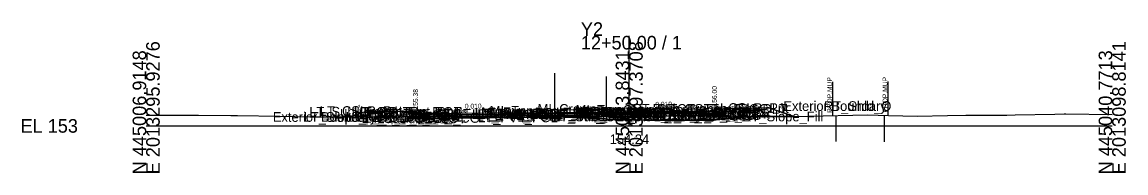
# Model space of a CAD drawing. Extents: x -26 to 203, y -10 to 6017.
# Drawn here: x -25.7 to 202.8, y 4990.3 to 5021.4 of the extents above; entities that cross this region are included whole.
import ezdxf

# ---------------------------------------------------------------- set-up
doc = ezdxf.new("R2010")
doc.units = 0
for name, color, linetype in [('Default', 7, 'Continuous'), ('Exist Cross Section Cell', 7, 'Continuous'), ('Exist XS Center Line Elevation Label', 7, 'Continuous'), ('Exist XS Ground Line', 7, 'Continuous'), ('Prop CMT Conc Surface', 7, 'Continuous'), ('Prop CMT Concrete Structures', 7, 'Continuous'), ('Prop CMT Pvmt Course 1', 7, 'Continuous'), ('Prop CMT Pvmt Course 1 CG', 7, 'Continuous'), ('Prop CMT Pvmt Course 1 Wedge', 7, 'Continuous'), ('Prop CMT Pvmt Course 2', 7, 'Continuous'), ('Prop CMT Pvmt Course 2 Wedge', 7, 'Continuous'), ('Prop CMT Pvmt Course 3', 7, 'Continuous'), ('Prop CMT Pvmt Surface', 7, 'Continuous'), ('Prop CMT Pvmt Wedge Surface 1', 7, 'Continuous'), ('Prop CMT Pvmt Wedge Surface 2', 7, 'Continuous'), ('Prop CMT Slope Grass', 7, 'Continuous'), ('Prop CMT Subgrade Earthwork', 7, 'Continuous'), ('Prop XS Earthwork Shape', 7, 'Continuous'), ('Prop XS Hydro Elevations', 7, 'Continuous'), ('Prop XS Label Text', 7, 'Continuous'), ('Prop XS SE Text', 7, 'Continuous'), ('Prop XS Side Slope Text', 7, 'Continuous'), ('Scratch_Level_0', 7, 'Continuous'), ('Scratch_Level_1', 7, 'Continuous'), ('Scratch_Level_3', 7, 'Continuous')]:
    doc.layers.add(name, color=color, linetype=linetype)

msp = doc.modelspace()

# ---------------------------------------------------------------- linework, layer by layer
at = {"layer": 'Exist Cross Section Cell'}
for p, q in [((100, 5000), (100, 5018.58)), ((0, 5000), (100, 5000)), ((100, 5000), (200, 5000))]:
    msp.add_line(p, q, dxfattribs=at)
at = {"layer": 'Exist XS Ground Line'}
msp.add_lwpolyline([(0, 5002.23), (6.99, 5002.25), (7.99, 5002.25), (10.86, 5002.24), (17.52, 5002.15), (18.9, 5002.15), (27.67, 5001.99), (33.86, 5001.88), (37.81, 5001.86), (43.4, 5001.84), (47.96, 5001.87), (55.66, 5001.97), (58.11, 5001.97), (67.91, 5001.92), (68.26, 5001.92), (69.94, 5001.96), (78.4, 5002.12), (79.89, 5002.1), (94.98, 5001.45), (96.16, 5001.33), (97.05, 5001.27), (100, 5001.24), (103.04, 5001.21), (107.68, 5001.17), (115.74, 5001.2), (117.56, 5001.19), (118.76, 5001.39), (119.14, 5001.44), (120.7, 5001.58), (125.45, 5001.92), (126.09, 5001.92), (132.22, 5001.92), (133.71, 5001.96), (137.05, 5002.02), (149.44, 5002.29), (153.67, 5002.17), (159.59, 5002.04), (165.92, 5002.17), (169.73, 5002.19), (178.18, 5002.25), (179.88, 5002.3), (188.1, 5002.44), (190.03, 5002.48), (190.43, 5002.48), (200, 5002.35)], dxfattribs=at)
at = {"layer": 'Prop CMT Conc Surface'}
for points in [[(51.26, 5002.97), (46.26, 5003.07)], [(55.76, 5002.38), (55.76, 5002.88), (55.26, 5002.88)], [(115.65, 5003.06), (117.65, 5003)], [(117.65, 5003), (117.66, 5003.5), (118.16, 5003.5)], [(57.76, 5002.48), (55.76, 5002.38)]]:
    msp.add_lwpolyline(points, dxfattribs=at)
at = {"layer": 'Prop CMT Concrete Structures'}
for p, q in [((84.64, 5002.92), (84.63, 5002.75)), ((85.39, 5003.17), (84.64, 5002.92)), ((90.11, 5003.36), (85.39, 5003.17)), ((94.57, 5003.27), (90.11, 5003.36)), ((95.32, 5003.02), (94.57, 5003.27)), ((95.33, 5002.86), (95.32, 5003.02))]:
    msp.add_line(p, q, dxfattribs=at)
for points in [[(46.26, 5002.74), (46.26, 5003.07)], [(46.26, 5003.07), (51.26, 5002.97)], [(51.26, 5002.64), (46.26, 5002.74)], [(51.26, 5002.97), (51.26, 5002.64)], [(57.76, 5002.48), (55.76, 5002.38), (55.76, 5002.88), (55.26, 5002.88)], [(55.26, 5002.88), (55.26, 5001.87), (57.76, 5001.9)], [(77.51, 5002.68), (98.45, 5002.89)], [(115.65, 5003.06), (117.65, 5003), (117.66, 5003.5), (118.16, 5003.5)], [(118.16, 5003.5), (118.15, 5002.5), (115.65, 5002.48)], [(115.65, 5002.48), (115.65, 5003.06)], [(128.43, 5003.72), (122.8, 5003.6)], [(122.8, 5003.6), (122.8, 5003.27)], [(122.8, 5003.27), (128.43, 5003.38)], [(128.43, 5003.38), (128.43, 5003.72)], [(57.76, 5001.9), (57.76, 5002.48)]]:
    msp.add_lwpolyline(points, dxfattribs=at)
at = {"layer": 'Prop CMT Pvmt Course 1'}
for points in [[(77.51, 5002.68), (57.76, 5002.48)], [(77.51, 5002.68), (98.45, 5002.89)], [(77.51, 5002.43), (77.51, 5002.68)], [(77.51, 5002.43), (77.51, 5002.68)], [(98.45, 5002.64), (77.51, 5002.43)], [(98.45, 5002.89), (115.65, 5003.06)], [(98.45, 5002.64), (98.45, 5002.89)], [(98.45, 5002.89), (98.45, 5002.64)], [(98.45, 5002.76), (98.45, 5002.64), (98.45, 5002.64)], [(115.65, 5002.81), (114.57, 5002.8)], [(115.65, 5003.06), (115.65, 5002.81)], [(57.76, 5002.48), (57.76, 5002.23)], [(57.76, 5002.23), (77.51, 5002.43)], [(77.51, 5002.55), (77.51, 5002.43), (77.51, 5002.43)]]:
    msp.add_lwpolyline(points, dxfattribs=at)
at = {"layer": 'Prop CMT Pvmt Course 1 CG'}
for points in [[(57.76, 5001.9), (54.76, 5001.87), (54.42, 5001.53)], [(54.42, 5001.53), (57.76, 5001.56)], [(57.76, 5001.65), (57.76, 5001.9)], [(115.65, 5002.48), (118.65, 5002.51), (118.98, 5002.18)], [(115.65, 5002.23), (115.65, 5002.48)], [(118.98, 5002.18), (115.65, 5002.14)]]:
    msp.add_lwpolyline(points, dxfattribs=at)
at = {"layer": 'Prop CMT Pvmt Course 1 Wedge'}
for points in [[(114.57, 5002.8), (107.68, 5002.73), (103.04, 5002.68), (98.45, 5002.64)], [(98.45, 5002.64), (98.45, 5002.76)]]:
    msp.add_lwpolyline(points, dxfattribs=at)
at = {"layer": 'Prop CMT Pvmt Course 2'}
for points in [[(77.51, 5002.43), (98.45, 5002.64)], [(98.45, 5002.64), (98.45, 5002.3)], [(114.57, 5002.8), (115.65, 5002.81)], [(114.57, 5002.47), (114.57, 5002.8)], [(115.65, 5002.81), (115.65, 5002.48)], [(77.51, 5002.43), (57.76, 5002.23)], [(57.76, 5002.23), (57.76, 5001.9)], [(57.76, 5001.9), (77.51, 5002.09)], [(77.51, 5002.09), (77.51, 5002.43)], [(98.45, 5002.3), (77.51, 5002.09)], [(115.65, 5002.48), (114.57, 5002.47)]]:
    msp.add_lwpolyline(points, dxfattribs=at)
at = {"layer": 'Prop CMT Pvmt Course 2 Wedge'}
for points in [[(98.45, 5002.64), (103.04, 5002.68), (107.68, 5002.73), (114.57, 5002.8)], [(98.45, 5002.3), (98.45, 5002.64)], [(114.57, 5002.8), (114.57, 5002.47)], [(114.57, 5002.47), (107.68, 5002.4), (103.04, 5002.35), (98.45, 5002.3)]]:
    msp.add_lwpolyline(points, dxfattribs=at)
at = {"layer": 'Prop CMT Pvmt Course 3'}
for points in [[(77.51, 5002.09), (57.76, 5001.9)], [(57.76, 5001.9), (57.76, 5001.56)], [(57.76, 5001.56), (77.51, 5001.76)], [(77.51, 5002.09), (98.45, 5002.3)], [(77.51, 5001.76), (77.51, 5002.09)], [(98.45, 5001.97), (77.51, 5001.76)], [(98.45, 5002.3), (98.45, 5001.97)], [(98.45, 5001.97), (118.2, 5002.17)], [(114.57, 5002.47), (115.65, 5002.48)], [(114.57, 5002.13), (114.57, 5002.47)], [(115.65, 5002.14), (114.57, 5002.13)], [(115.65, 5002.48), (115.65, 5002.14)]]:
    msp.add_lwpolyline(points, dxfattribs=at)
at = {"layer": 'Prop CMT Pvmt Surface'}
for points in [[(77.51, 5002.68), (57.76, 5002.48)], [(77.51, 5002.68), (98.45, 5002.89)], [(98.45, 5002.89), (115.65, 5003.06)]]:
    msp.add_lwpolyline(points, dxfattribs=at)
at = {"layer": 'Prop CMT Pvmt Wedge Surface 1'}
for points in [[(98.45, 5002.89), (98.45, 5002.64), (98.45, 5002.64), (98.45, 5002.76)], [(114.57, 5002.8), (115.65, 5002.81)], [(115.65, 5002.81), (115.65, 5003.06)]]:
    msp.add_lwpolyline(points, dxfattribs=at)
at = {"layer": 'Prop CMT Pvmt Wedge Surface 2'}
for points in [[(98.45, 5002.89), (98.45, 5002.64)], [(98.45, 5002.64), (115.65, 5002.81)], [(115.65, 5002.81), (115.65, 5003.06)]]:
    msp.add_lwpolyline(points, dxfattribs=at)
at = {"layer": 'Prop CMT Slope Grass'}
for points in [[(55.26, 5002.88), (45.76, 5003.07), (42.08, 5001.84)], [(118.16, 5003.5), (128.93, 5003.72)], [(128.93, 5003.72), (134.18, 5001.97)]]:
    msp.add_lwpolyline(points, dxfattribs=at)
at = {"layer": 'Prop CMT Subgrade Earthwork'}
for points in [[(57.76, 5001.56), (54.42, 5001.53), (53.03, 5002.92)], [(115.65, 5002.14), (118.98, 5002.18), (120.35, 5003.54)], [(77.51, 5001.76), (57.76, 5001.56)], [(77.51, 5001.76), (98.45, 5001.97)], [(114.57, 5002.13), (98.45, 5001.97)], [(114.57, 5002.13), (115.65, 5002.14)]]:
    msp.add_lwpolyline(points, dxfattribs=at)
at = {"layer": 'Prop XS Earthwork Shape'}
for points in [[(54, 5001.95), (53.03, 5002.93), (45.76, 5003.07), (42.08, 5001.84), (43.4, 5001.84), (47.96, 5001.87)], [(42.08, 5001.84), (43.4, 5001.84), (47.96, 5001.87), (54, 5001.95), (53.03, 5002.93), (45.76, 5003.07)], [(54, 5001.95), (53.03, 5002.93), (45.76, 5003.07), (42.08, 5001.84), (43.4, 5001.84), (47.96, 5001.87)], [(45.76, 5003.07), (42.08, 5001.84), (43.4, 5001.84), (47.96, 5001.87), (54, 5001.95), (53.03, 5002.93)], [(97.05, 5001.27), (100, 5001.24), (103.04, 5001.21), (107.68, 5001.17), (115.74, 5001.2), (117.56, 5001.19), (118.76, 5001.39), (119.14, 5001.44), (120.7, 5001.58), (125.45, 5001.92), (126.09, 5001.92), (132.22, 5001.92), (133.71, 5001.96), (134.18, 5001.97), (128.93, 5003.72), (128.43, 5003.71), (128.43, 5003.38), (122.8, 5003.27), (122.8, 5003.59), (120.35, 5003.54), (118.98, 5002.18), (115.65, 5002.14), (114.57, 5002.13), (98.45, 5001.97), (85.88, 5001.85), (94.98, 5001.45), (96.16, 5001.33)], [(128.43, 5003.71), (128.93, 5003.72), (134.18, 5001.97), (133.71, 5001.96), (132.22, 5001.92), (126.09, 5001.92), (125.45, 5001.92), (120.7, 5001.58), (119.14, 5001.44), (118.76, 5001.39), (117.56, 5001.19), (115.74, 5001.2), (107.68, 5001.17), (103.04, 5001.21), (100, 5001.24), (97.05, 5001.27), (96.16, 5001.33), (94.98, 5001.45), (85.88, 5001.85), (98.45, 5001.97), (114.57, 5002.13), (115.65, 5002.14), (118.98, 5002.18), (120.35, 5003.54), (122.8, 5003.59), (122.8, 5003.27), (128.43, 5003.38)], [(97.05, 5001.27), (100, 5001.24), (103.04, 5001.21), (107.68, 5001.17), (115.74, 5001.2), (117.56, 5001.19), (118.76, 5001.39), (119.14, 5001.44), (120.7, 5001.58), (125.45, 5001.92), (126.09, 5001.92), (132.22, 5001.92), (133.71, 5001.96), (134.18, 5001.97), (128.93, 5003.72), (128.43, 5003.71), (128.43, 5003.38), (122.8, 5003.27), (122.8, 5003.59), (120.35, 5003.54), (118.98, 5002.18), (115.65, 5002.14), (114.57, 5002.13), (98.45, 5001.97), (85.88, 5001.85), (94.98, 5001.45), (96.16, 5001.33)], [(100, 5001.24), (103.04, 5001.21), (107.68, 5001.17), (115.74, 5001.2), (117.56, 5001.19), (118.76, 5001.39), (119.14, 5001.44), (120.7, 5001.58), (125.45, 5001.92), (126.09, 5001.92), (132.22, 5001.92), (133.71, 5001.96), (134.18, 5001.97), (128.93, 5003.72), (128.43, 5003.71), (128.43, 5003.38), (122.8, 5003.27), (122.8, 5003.59), (120.35, 5003.54), (118.98, 5002.18), (115.65, 5002.14), (114.57, 5002.13), (98.45, 5001.97), (85.88, 5001.85), (94.98, 5001.45), (96.16, 5001.33), (97.05, 5001.27)], [(54, 5001.95), (55.26, 5001.97), (55.26, 5001.87), (57.76, 5001.9), (57.76, 5001.97), (58.11, 5001.97), (67.91, 5001.92), (68.26, 5001.92), (69.94, 5001.96), (78.4, 5002.12), (79.89, 5002.1), (85.88, 5001.85), (77.51, 5001.76), (57.76, 5001.56), (54.42, 5001.53)], [(54, 5001.95), (55.26, 5001.97), (55.26, 5001.87), (57.76, 5001.9), (57.76, 5001.97), (58.11, 5001.97), (67.91, 5001.92), (68.26, 5001.92), (69.94, 5001.96), (78.4, 5002.12), (79.89, 5002.1), (85.88, 5001.85), (77.51, 5001.76), (57.76, 5001.56), (54.42, 5001.53)], [(54, 5001.95), (55.26, 5001.97), (55.26, 5001.87), (57.76, 5001.9), (57.76, 5001.97), (58.11, 5001.97), (67.91, 5001.92), (68.26, 5001.92), (69.94, 5001.96), (78.4, 5002.12), (79.89, 5002.1), (85.88, 5001.85), (77.51, 5001.76), (57.76, 5001.56), (54.42, 5001.53)], [(54, 5001.95), (55.26, 5001.97), (55.26, 5001.87), (57.76, 5001.9), (57.76, 5001.97), (58.11, 5001.97), (67.91, 5001.92), (68.26, 5001.92), (69.94, 5001.96), (78.4, 5002.12), (79.89, 5002.1), (85.88, 5001.85), (77.51, 5001.76), (57.76, 5001.56), (54.42, 5001.53)], [(55.66, 5001.97), (57.76, 5001.97), (57.76, 5001.9), (55.26, 5001.87), (55.26, 5001.97)], [(55.66, 5001.97), (57.76, 5001.97), (57.76, 5001.9), (55.26, 5001.87), (55.26, 5001.97)], [(55.66, 5001.97), (57.76, 5001.97), (57.76, 5001.9), (55.26, 5001.87), (55.26, 5001.97)], [(55.66, 5001.97), (57.76, 5001.97), (57.76, 5001.9), (55.26, 5001.87), (55.26, 5001.97)]]:
    msp.add_lwpolyline(points, close=True, dxfattribs=at)
at = {"layer": 'Prop XS Label Text'}
for p, q in [((142.11, 5009.13), (142.11, 5002.13)), ((153.57, 5009.17), (153.57, 5002.17))]:
    msp.add_line(p, q, dxfattribs=at)
at = {"layer": 'Scratch_Level_1'}
for p, q in [((142.78, 5002.14), (142.78, 4996.79)), ((152.79, 5002.19), (152.79, 4996.68))]:
    msp.add_line(p, q, dxfattribs=at)
at = {"layer": 'Scratch_Level_3'}
for p, q in [((84.63, 5002.75), (84.63, 5010.88)), ((95.33, 5002.86), (95.33, 5010.19))]:
    msp.add_line(p, q, dxfattribs=at)

# ---------------------------------------------------------------- texts
at = {"layer": 'Default'}
msp.add_text('-', height=0.0001, dxfattribs=at).set_placement((0, 5000))
at = {"layer": 'Exist Cross Section Cell'}
for s, p in [('Y2', (90, 5018.58)), ('12+50.00 / 1', (90, 5015.78)), ('EL 153', (-26, 4998.6))]:
    msp.add_text(s, height=2.8, dxfattribs=at).set_placement(p)
for s, p in [('E 2013295.9276', (2.8, 4990)), ('E 2013197.3708', (102.8, 4990)), ('E 2013098.8141', (202.8, 4990)), ('N 445006.9148', (0, 4990)), ('N 445023.8431', (100, 4990)), ('N 445040.7713', (200, 4990))]:
    msp.add_text(s, height=2.8, rotation=90, dxfattribs=at).set_placement(p)
at = {"layer": 'Exist XS Center Line Elevation Label'}
msp.add_text('154.24', height=2, dxfattribs=at).set_placement((95.96, 4996.24))
at = {"layer": 'Prop XS Hydro Elevations'}
for s, p in [('155.38', (56.26, 5003.38)), ('156.00', (118.15, 5004))]:
    msp.add_text(s, height=1, rotation=90, dxfattribs=at).set_placement(p)
at = {"layer": 'Prop XS Label Text'}
for p in [(142.01, 5002.7), (153.47, 5002.75)]:
    msp.add_text('PROP.MUP', height=1, rotation=90, dxfattribs=at).set_placement(p)
at = {"layer": 'Prop XS SE Text'}
for p in [(105.41, 5003.96), (65.99, 5003.56)]:
    msp.add_text('0.010', height=1, rotation=0.5729, dxfattribs=at).set_placement(p)
at = {"layer": 'Prop XS Side Slope Text'}
for rotation, p in [(18.4349, (42.93, 5002.92)), (341.5651, (131.04, 5003.8))]:
    msp.add_text('3:1', height=1, rotation=rotation, dxfattribs=at).set_placement(p)
at = {"layer": 'Scratch_Level_0'}
for s, p in [('Exterior Boundary', (131.92, 5003.09)), ('RT_Shld_O', (140.31, 5003.09)), ('Exterior Boundary', (26.22, 5000.84)), ('LT_Slope_Fill', (32.6, 5000.84)), ('LT_Sub_Trench_Out_DLT', (33.76, 5001.92)), ('LT_CSLP_Pnt', (35.93, 5002.07)), ('LT_CG1_Shelf_Out', (41.31, 5000.87)), ('LT_CG_Top_Face', (43.02, 5001.88)), ('LT_CG_Top_BOC', (43.54, 5001.88)), ('LT_CG_Bot_BOC', (43.57, 5000.87)), ('LT_CG_Top_Gut', (43.99, 5001.38)), ('LT_Sub_OEOP', (44.61, 5000.61)), ('LT_Sub_OEOT_CG', (45.13, 5000.65)), ('LT_CG_Bot_IE', (47.67, 5000.9)), ('LT_Sub_OEOT', (47.84, 5000.56)), ('LT_PV2_OEOT', (47.93, 5001.23)), ('LT_PV3_OEOT', (47.93, 5000.9)), ('LT_PV1_OEOT', (48.5, 5001.48)), ('LT_PV2_IEEOP', (67.46, 5001.43)), ('LT_PV1_IEEOP', (68.03, 5001.55)), ('LT_PV2_PGL1', (68.39, 5001.43)), ('LT_PV3_PGL1', (68.39, 5001.09)), ('LT_PV2_PGL', (68.72, 5001.43)), ('LT_PV4_PGL', (68.72, 5000.76)), ('LT_PV1_PGL', (69.29, 5001.68)), ('MI_Face In', (69.41, 5001.84)), ('MI_Top In', (71.12, 5002.09)), ('MI_Crown', (81.05, 5002.5)), ('LT_Sub_OEEOP', (84.19, 5000.94)), ('LT_PV2_OEEOP', (84.29, 5001.6)), ('LT_PV3_OEEOP', (84.29, 5001.27)), ('LT_PV1_OEEOP', (84.86, 5001.73)), ('RT_PV2_IEEOP', (88.35, 5001.64)), ('MI_Face Out', (88.71, 5002.05)), ('MI_Top Out', (88.92, 5002.3)), ('RT_PV1_IEEOP', (88.92, 5001.76)), ('RT_PV2_PGL1', (89.28, 5001.64)), ('RT_PV3_PGL1', (89.28, 5001.3)), ('RT_PV2_PGL', (89.61, 5001.64)), ('RT_PV4_PGL', (89.61, 5000.97)), ('MI_Bot Out', (89.71, 5001.89)), ('RT_PV1_PGL', (90.18, 5001.89)), ('RT_Sub_Trench_Out_DLT', (100.7, 5002.54)), ('RT_Sub_OEOT_CG', (102.98, 5001.23)), ('RT_Sub_OEEOP', (103.73, 5001.13)), ('RT_PV2_OEEOP', (103.83, 5001.8)), ('RT_PV3_OEEOP', (103.83, 5001.47)), ('RT_PV1_OEEOP', (104.39, 5001.92)), ('RT_CG_Top_Face', (104.87, 5002.5)), ('RT_CG1_Shelf_Out', (105.16, 5001.51)), ('RT_CG_Bot_IE', (105.52, 5001.48)), ('RT_Sub_OEOT', (105.69, 5001.14)), ('RT_PV2_OEOT', (105.78, 5001.81)), ('RT_PV3_OEOT', (105.78, 5001.48)), ('RT_CG_Top_Gut', (105.84, 5002)), ('RT_PV1_OEOT', (106.35, 5002.06)), ('RT_CG_Top_BOC', (106.39, 5002.5)), ('RT_CG_Bot_BOC', (106.42, 5001.5)), ('RT_Sub_OEOP', (108.97, 5001.26)), ('CSLP_Pnt', (120.52, 5002.69)), ('RT_Slope_Fill', (123.38, 5000.94))]:
    msp.add_text(s, height=2, dxfattribs=at).set_placement(p)

doc.saveas('drawing.dxf')
